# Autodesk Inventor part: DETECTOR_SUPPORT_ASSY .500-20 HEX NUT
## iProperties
Shininess: 64.0
Length Units: 11272
Angle Units: 11279
Time Units: 11290
Mass Units: 11286
Length Display Precision: 3
Angle Display Precision: 2
Compacted: True
Part Number: DETECTOR_SUPPORT_ASSY .500-20 HEX NUT
Document SubType Name: Modeling
Created: 2004-08
Designer: John Blackburn
Material: MILD_STEEL
Manufacturer: Standard
Standards Organization: Custom
Density: 0.0
Volumn: 0.0
Area: 0.0
PropertySet Name: Model Information
Control State: 0
Master: False
Checked Out: False
Author: John Blackburn
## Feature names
1. Base1
